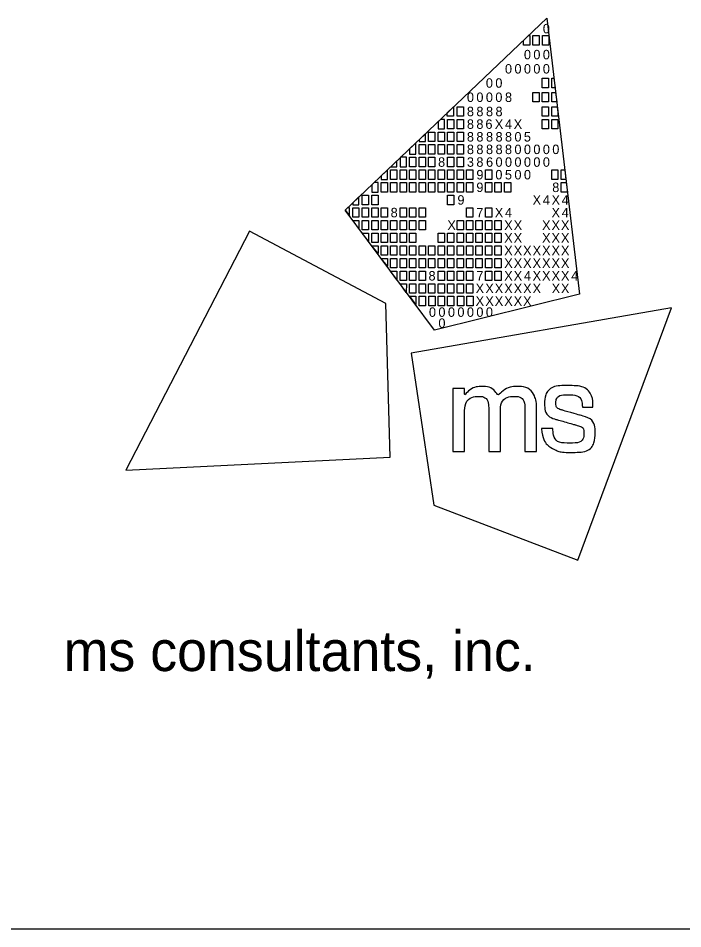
# Model space of a CAD drawing. Extents: x 0 to 34, y 0 to 22.
# Drawn here: x 32.048 to 33.205, y 2.5 to 4.086 of the extents above; entities that cross this region are included whole.
import ezdxf

# ---------------------------------------------------------------- set-up
doc = ezdxf.new("R2010")
doc.units = 0
doc.layers.add('SH_Border', color=7, linetype='Continuous')
doc.layers.add('SH_Data', color=7, linetype='Continuous')

msp = doc.modelspace()

# ---------------------------------------------------------------- linework, layer by layer
at = {"layer": 'SH_Border'}
for p, q in [((32.6175, 3.7519), (32.9688, 4.0861)), ((32.9688, 4.0861), (32.9688, 4.0861)), ((32.9688, 4.0861), (33.0253, 3.6052)), ((32.773, 3.543), (32.6175, 3.7519)), ((33.0253, 3.6052), (32.773, 3.543)), ((32, 2.5), (33.5, 2.5))]:
    msp.add_line(p, q, dxfattribs=at)
for points in [[(32.9279, 4.0472), (32.9369, 4.0558), (32.9389, 4.0558), (32.9389, 4.0393), (32.9279, 4.0393)], [(32.9444, 4.0558), (32.9554, 4.0558), (32.9554, 4.0393), (32.9444, 4.0393)], [(32.9609, 4.0558), (32.9719, 4.0558), (32.9719, 4.0393), (32.9609, 4.0393)], [(32.9606, 3.9815), (32.9716, 3.9815), (32.9716, 3.965), (32.9606, 3.965)], [(32.9771, 3.9815), (32.9811, 3.9815), (32.983, 3.965), (32.9771, 3.965)], [(32.9441, 3.9567), (32.9551, 3.9567), (32.9551, 3.9402), (32.9441, 3.9402)], [(32.9606, 3.9567), (32.9716, 3.9567), (32.9716, 3.9402), (32.9606, 3.9402)], [(32.9771, 3.9567), (32.984, 3.9567), (32.9859, 3.9402), (32.9771, 3.9402)], [(32.7953, 3.9211), (32.8064, 3.9316), (32.8064, 3.9154), (32.7953, 3.9154)], [(32.8123, 3.9319), (32.8233, 3.9319), (32.8233, 3.9154), (32.8123, 3.9154)], [(32.9606, 3.9319), (32.9716, 3.9319), (32.9716, 3.9154), (32.9606, 3.9154)], [(32.9771, 3.9319), (32.9869, 3.9319), (32.9881, 3.9218), (32.9881, 3.9154), (32.9771, 3.9154)], [(32.7958, 3.9099), (32.8068, 3.9099), (32.8068, 3.8934), (32.7958, 3.8934)], [(32.8123, 3.9099), (32.8233, 3.9099), (32.8233, 3.8934), (32.8123, 3.8934)], [(32.9606, 3.9099), (32.9716, 3.9099), (32.9716, 3.8934), (32.9606, 3.8934)], [(32.9771, 3.9099), (32.9881, 3.9099), (32.9881, 3.8934), (32.9771, 3.8934)], [(32.7627, 3.8879), (32.7737, 3.8879), (32.7737, 3.8714), (32.7627, 3.8714)], [(32.7793, 3.8879), (32.7903, 3.8879), (32.7903, 3.8714), (32.7793, 3.8714)], [(32.7958, 3.8879), (32.8068, 3.8879), (32.8068, 3.8714), (32.7958, 3.8714)], [(32.8123, 3.8879), (32.8233, 3.8879), (32.8233, 3.8714), (32.8123, 3.8714)], [(32.7462, 3.8659), (32.7572, 3.8659), (32.7572, 3.8494), (32.7462, 3.8494)], [(32.7627, 3.8659), (32.7737, 3.8659), (32.7737, 3.8494), (32.7627, 3.8494)], [(32.7793, 3.8659), (32.7903, 3.8659), (32.7903, 3.8494), (32.7793, 3.8494)], [(32.7958, 3.8659), (32.8068, 3.8659), (32.8068, 3.8494), (32.7958, 3.8494)], [(32.8123, 3.8659), (32.8233, 3.8659), (32.8233, 3.8494), (32.8123, 3.8494)], [(32.7297, 3.8439), (32.7407, 3.8439), (32.7407, 3.8273), (32.7297, 3.8273)], [(32.7462, 3.8439), (32.7572, 3.8439), (32.7572, 3.8273), (32.7462, 3.8273)], [(32.7627, 3.8439), (32.7737, 3.8439), (32.7737, 3.8273), (32.7627, 3.8273)], [(32.7958, 3.8439), (32.8068, 3.8439), (32.8068, 3.8273), (32.7958, 3.8273)], [(32.8123, 3.8439), (32.8233, 3.8439), (32.8233, 3.8273), (32.8123, 3.8273)], [(32.6967, 3.8218), (32.7077, 3.8218), (32.7077, 3.8053), (32.6967, 3.8053)], [(32.7132, 3.8218), (32.7242, 3.8218), (32.7242, 3.8053), (32.7132, 3.8053)], [(32.7297, 3.8218), (32.7407, 3.8218), (32.7407, 3.8053), (32.7297, 3.8053)], [(32.7462, 3.8218), (32.7572, 3.8218), (32.7572, 3.8053), (32.7462, 3.8053)], [(32.7627, 3.8218), (32.7737, 3.8218), (32.7737, 3.8053), (32.7627, 3.8053)], [(32.7793, 3.8218), (32.7903, 3.8218), (32.7903, 3.8053), (32.7793, 3.8053)], [(32.7958, 3.8218), (32.8068, 3.8218), (32.8068, 3.8053), (32.7958, 3.8053)], [(32.8123, 3.8218), (32.8233, 3.8218), (32.8233, 3.8053), (32.8123, 3.8053)], [(32.8288, 3.8218), (32.8398, 3.8218), (32.8398, 3.8053), (32.8288, 3.8053)], [(32.8618, 3.8218), (32.8728, 3.8218), (32.8728, 3.8053), (32.8618, 3.8053)], [(32.9771, 3.8218), (32.9881, 3.8218), (32.9881, 3.8053), (32.9771, 3.8053)], [(32.9935, 3.8218), (32.9998, 3.8218), (33.0018, 3.8053), (32.9935, 3.8053)], [(32.6802, 3.7998), (32.6912, 3.7998), (32.6912, 3.7833), (32.6802, 3.7833)], [(32.6967, 3.7998), (32.7077, 3.7998), (32.7077, 3.7833), (32.6967, 3.7833)], [(32.7132, 3.7998), (32.7242, 3.7998), (32.7242, 3.7833), (32.7132, 3.7833)], [(32.7297, 3.7998), (32.7407, 3.7998), (32.7407, 3.7833), (32.7297, 3.7833)], [(32.7462, 3.7998), (32.7572, 3.7998), (32.7572, 3.7833), (32.7462, 3.7833)], [(32.7627, 3.7998), (32.7737, 3.7998), (32.7737, 3.7833), (32.7627, 3.7833)], [(32.7793, 3.7998), (32.7903, 3.7998), (32.7903, 3.7833), (32.7793, 3.7833)], [(32.7958, 3.7998), (32.8068, 3.7998), (32.8068, 3.7833), (32.7958, 3.7833)], [(32.8123, 3.7998), (32.8233, 3.7998), (32.8233, 3.7833), (32.8123, 3.7833)], [(32.8288, 3.7998), (32.8398, 3.7998), (32.8398, 3.7833), (32.8288, 3.7833)], [(32.8618, 3.7998), (32.8728, 3.7998), (32.8728, 3.7833), (32.8618, 3.7833)], [(32.8783, 3.7998), (32.8893, 3.7998), (32.8893, 3.7833), (32.8783, 3.7833)], [(32.8947, 3.7998), (32.9057, 3.7998), (32.9057, 3.7833), (32.8947, 3.7833)], [(32.9935, 3.7998), (33.0024, 3.7998), (33.0044, 3.7833), (32.9935, 3.7833)], [(32.6471, 3.7778), (32.6581, 3.7778), (32.6581, 3.7613), (32.6471, 3.7613)], [(32.6637, 3.7778), (32.6747, 3.7778), (32.6747, 3.7613), (32.6637, 3.7613)], [(32.7958, 3.7778), (32.8068, 3.7778), (32.8068, 3.7613), (32.7958, 3.7613)], [(32.6306, 3.7558), (32.6416, 3.7558), (32.6416, 3.7393), (32.6306, 3.7393)], [(32.6471, 3.7558), (32.6581, 3.7558), (32.6581, 3.7393), (32.6471, 3.7393)], [(32.6637, 3.7558), (32.6747, 3.7558), (32.6747, 3.7393), (32.6637, 3.7393)], [(32.6802, 3.7558), (32.6912, 3.7558), (32.6912, 3.7393), (32.6802, 3.7393)], [(32.7132, 3.7558), (32.7242, 3.7558), (32.7242, 3.7393), (32.7132, 3.7393)], [(32.7297, 3.7558), (32.7407, 3.7558), (32.7407, 3.7393), (32.7297, 3.7393)], [(32.7462, 3.7558), (32.7572, 3.7558), (32.7572, 3.7393), (32.7462, 3.7393)], [(32.8288, 3.7558), (32.8398, 3.7558), (32.8398, 3.7393), (32.8288, 3.7393)], [(32.8618, 3.7558), (32.8728, 3.7558), (32.8728, 3.7393), (32.8618, 3.7393)], [(32.6306, 3.7338), (32.6416, 3.7338), (32.6416, 3.72)], [(32.6471, 3.7338), (32.6581, 3.7338), (32.6581, 3.7173), (32.6471, 3.7173)], [(32.6637, 3.7338), (32.6747, 3.7338), (32.6747, 3.7173), (32.6637, 3.7173)], [(32.6802, 3.7338), (32.6912, 3.7338), (32.6912, 3.7173), (32.6802, 3.7173)], [(32.6967, 3.7338), (32.7077, 3.7338), (32.7077, 3.7173), (32.6967, 3.7173)], [(32.7132, 3.7338), (32.7242, 3.7338), (32.7242, 3.7173), (32.7132, 3.7173)], [(32.7297, 3.7338), (32.7407, 3.7338), (32.7407, 3.7173), (32.7297, 3.7173)], [(32.7462, 3.7338), (32.7572, 3.7338), (32.7572, 3.7173), (32.7462, 3.7173)], [(32.8123, 3.7338), (32.8233, 3.7338), (32.8233, 3.7173), (32.8123, 3.7173)], [(32.8288, 3.7338), (32.8398, 3.7338), (32.8398, 3.7173), (32.8288, 3.7173)], [(32.8453, 3.7338), (32.8563, 3.7338), (32.8563, 3.7173), (32.8453, 3.7173)], [(32.8618, 3.7338), (32.8728, 3.7338), (32.8728, 3.7173), (32.8618, 3.7173)], [(32.8783, 3.7338), (32.8893, 3.7338), (32.8893, 3.7173), (32.8783, 3.7173)], [(32.6471, 3.7117), (32.6581, 3.7117), (32.6581, 3.698)], [(32.6637, 3.7117), (32.6747, 3.7117), (32.6747, 3.6952), (32.6637, 3.6952)], [(32.6802, 3.7117), (32.6912, 3.7117), (32.6912, 3.6952), (32.6802, 3.6952)], [(32.6967, 3.7117), (32.7077, 3.7117), (32.7077, 3.6952), (32.6967, 3.6952)], [(32.7132, 3.7117), (32.7242, 3.7117), (32.7242, 3.6952), (32.7132, 3.6952)], [(32.7297, 3.7117), (32.7407, 3.7117), (32.7407, 3.6952), (32.7297, 3.6952)], [(32.7793, 3.7117), (32.7903, 3.7117), (32.7903, 3.6952), (32.7793, 3.6952)], [(32.7958, 3.7117), (32.8068, 3.7117), (32.8068, 3.6952), (32.7958, 3.6952)], [(32.8123, 3.7117), (32.8233, 3.7117), (32.8233, 3.6952), (32.8123, 3.6952)], [(32.8288, 3.7117), (32.8398, 3.7117), (32.8398, 3.6952), (32.8288, 3.6952)], [(32.8453, 3.7117), (32.8563, 3.7117), (32.8563, 3.6952), (32.8453, 3.6952)], [(32.8618, 3.7117), (32.8728, 3.7117), (32.8728, 3.6952), (32.8618, 3.6952)], [(32.8783, 3.7117), (32.8893, 3.7117), (32.8893, 3.6952), (32.8783, 3.6952)], [(32.6637, 3.6897), (32.6747, 3.6897), (32.6747, 3.676)], [(32.6747, 3.6897), (32.6747, 3.6897), (32.6747, 3.6897)], [(32.6802, 3.6897), (32.6912, 3.6897), (32.6912, 3.6732), (32.6802, 3.6732)], [(32.6967, 3.6897), (32.7077, 3.6897), (32.7077, 3.6732), (32.6967, 3.6732)], [(32.7132, 3.6897), (32.7242, 3.6897), (32.7242, 3.6732), (32.7132, 3.6732)], [(32.7297, 3.6897), (32.7407, 3.6897), (32.7407, 3.6732), (32.7297, 3.6732)], [(32.7462, 3.6897), (32.7572, 3.6897), (32.7572, 3.6732), (32.7462, 3.6732)], [(32.7627, 3.6897), (32.7737, 3.6897), (32.7737, 3.6732), (32.7627, 3.6732)], [(32.7793, 3.6897), (32.7903, 3.6897), (32.7903, 3.6732), (32.7793, 3.6732)], [(32.7958, 3.6897), (32.8068, 3.6897), (32.8068, 3.6732), (32.7958, 3.6732)], [(32.8123, 3.6897), (32.8233, 3.6897), (32.8233, 3.6732), (32.8123, 3.6732)], [(32.8288, 3.6897), (32.8398, 3.6897), (32.8398, 3.6732), (32.8288, 3.6732)], [(32.8453, 3.6897), (32.8563, 3.6897), (32.8563, 3.6732), (32.8453, 3.6732)], [(32.8618, 3.6897), (32.8728, 3.6897), (32.8728, 3.6732), (32.8618, 3.6732)], [(32.8783, 3.6897), (32.8893, 3.6897), (32.8893, 3.6732), (32.8783, 3.6732)], [(32.6802, 3.6677), (32.6912, 3.6677), (32.6912, 3.654)], [(32.6967, 3.6677), (32.7077, 3.6677), (32.7077, 3.6512), (32.6967, 3.6512)], [(32.7132, 3.6677), (32.7242, 3.6677), (32.7242, 3.6512), (32.7132, 3.6512)], [(32.7297, 3.6677), (32.7407, 3.6677), (32.7407, 3.6512), (32.7297, 3.6512)], [(32.7462, 3.6677), (32.7572, 3.6677), (32.7572, 3.6512), (32.7462, 3.6512)], [(32.7627, 3.6677), (32.7737, 3.6677), (32.7737, 3.6512), (32.7627, 3.6512)], [(32.7793, 3.6677), (32.7903, 3.6677), (32.7903, 3.6512), (32.7793, 3.6512)], [(32.7958, 3.6677), (32.8068, 3.6677), (32.8068, 3.6512), (32.7958, 3.6512)], [(32.8123, 3.6677), (32.8233, 3.6677), (32.8233, 3.6512), (32.8123, 3.6512)], [(32.8288, 3.6677), (32.8398, 3.6677), (32.8398, 3.6512), (32.8288, 3.6512)], [(32.8453, 3.6677), (32.8563, 3.6677), (32.8563, 3.6512), (32.8453, 3.6512)], [(32.8618, 3.6677), (32.8728, 3.6677), (32.8728, 3.6512), (32.8618, 3.6512)], [(32.8783, 3.6677), (32.8893, 3.6677), (32.8893, 3.6512), (32.8783, 3.6512)], [(32.7077, 3.6305), (32.6965, 3.6457), (32.7077, 3.6457)], [(32.7132, 3.6457), (32.7242, 3.6457), (32.7242, 3.6292), (32.7132, 3.6292)], [(32.7297, 3.6457), (32.7407, 3.6457), (32.7407, 3.6292), (32.7297, 3.6292)], [(32.7462, 3.6457), (32.7572, 3.6457), (32.7572, 3.6292), (32.7462, 3.6292)], [(32.7793, 3.6457), (32.7903, 3.6457), (32.7903, 3.6292), (32.7793, 3.6292)], [(32.7958, 3.6457), (32.8068, 3.6457), (32.8068, 3.6292), (32.7958, 3.6292)], [(32.8123, 3.6457), (32.8233, 3.6457), (32.8233, 3.6292), (32.8123, 3.6292)], [(32.8288, 3.6457), (32.8398, 3.6457), (32.8398, 3.6292), (32.8288, 3.6292)], [(32.8618, 3.6457), (32.8728, 3.6457), (32.8728, 3.6292), (32.8618, 3.6292)], [(32.8783, 3.6457), (32.8893, 3.6457), (32.8893, 3.6292), (32.8783, 3.6292)], [(32.724, 3.6082), (32.7132, 3.6237), (32.7242, 3.6237)], [(32.7297, 3.6237), (32.7407, 3.6237), (32.7407, 3.6072), (32.7297, 3.6072)], [(32.7462, 3.6237), (32.7572, 3.6237), (32.7572, 3.6072), (32.7462, 3.6072)], [(32.7627, 3.6237), (32.7737, 3.6237), (32.7737, 3.6072), (32.7627, 3.6072)], [(32.7793, 3.6237), (32.7903, 3.6237), (32.7903, 3.6072), (32.7793, 3.6072)], [(32.7958, 3.6237), (32.8068, 3.6237), (32.8068, 3.6072), (32.7958, 3.6072)], [(32.8123, 3.6237), (32.8233, 3.6237), (32.8233, 3.6072), (32.8123, 3.6072)], [(32.8288, 3.6237), (32.8398, 3.6237), (32.8398, 3.6072), (32.8288, 3.6072)], [(32.7302, 3.6017), (32.7407, 3.6017), (32.7408, 3.5875)], [(32.7463, 3.6017), (32.7573, 3.6017), (32.7573, 3.5852), (32.7463, 3.5852)], [(32.763, 3.6017), (32.774, 3.6017), (32.774, 3.5852), (32.763, 3.5852)], [(32.7794, 3.6017), (32.7904, 3.6017), (32.7904, 3.5852), (32.7794, 3.5852)], [(32.796, 3.6017), (32.807, 3.6017), (32.807, 3.5852), (32.796, 3.5852)], [(32.8129, 3.6017), (32.8239, 3.6017), (32.8239, 3.5851), (32.8129, 3.5851)], [(32.8296, 3.6017), (32.8406, 3.6017), (32.8406, 3.5851), (32.8296, 3.5851)]]:
    msp.add_lwpolyline(points, close=True, dxfattribs=at)
for points in [[(32.7903, 3.9099), (32.7836, 3.9099), (32.7793, 3.9058), (32.7793, 3.8934), (32.7903, 3.8934), (32.7903, 3.9099)], [(32.7572, 3.8849), (32.7462, 3.8744), (32.7462, 3.8714), (32.7572, 3.8714), (32.7572, 3.8849)], [(32.7407, 3.8691), (32.7297, 3.8587), (32.7297, 3.8494), (32.7407, 3.8494), (32.7407, 3.8691)], [(32.7242, 3.8439), (32.7141, 3.8439), (32.7132, 3.843), (32.7132, 3.8273), (32.7242, 3.8273), (32.7242, 3.8439)], [(32.7077, 3.8377), (32.6968, 3.8273), (32.7077, 3.8273), (32.7077, 3.8377)], [(32.6912, 3.822), (32.6802, 3.8115), (32.6802, 3.8053), (32.6912, 3.8053), (32.6912, 3.822)], [(32.6747, 3.7998), (32.6679, 3.7998), (32.6637, 3.7958), (32.6637, 3.7833), (32.6747, 3.7833), (32.6747, 3.7998)], [(32.6416, 3.7749), (32.6306, 3.7644), (32.6306, 3.7613), (32.6416, 3.7613), (32.6416, 3.7749)], [(32.6251, 3.7558), (32.6216, 3.7558), (32.6175, 3.7519), (32.6251, 3.7417), (32.6251, 3.7558)], [(32.4512, 3.7149), (32.2359, 3.2988), (32.6956, 3.3215), (32.6884, 3.5892), (32.4512, 3.7149)], [(33.0229, 3.1422), (33.1859, 3.5814), (32.7324, 3.5029), (32.7722, 3.2381), (33.0229, 3.1422)]]:
    msp.add_lwpolyline(points, dxfattribs=at)
for points in [[(32.8048, 3.3315), (32.8048, 3.3315), (32.8048, 3.4409), (32.8048, 3.4409), (32.8048, 3.4409), (32.8255, 3.4409), (32.8255, 3.4409), (32.8255, 3.4409), (32.8255, 3.4297), (32.8255, 3.4297), (32.8346, 3.4399), (32.8457, 3.4445), (32.8555, 3.4445), (32.8688, 3.4445), (32.8791, 3.4372), (32.8837, 3.4266), (32.8915, 3.4381), (32.905, 3.4446), (32.9166, 3.4446), (32.9325, 3.4446), (32.9451, 3.435), (32.9494, 3.4213), (32.9494, 3.4212), (32.9494, 3.4212), (32.9494, 3.4212), (32.9501, 3.419), (32.9506, 3.4172), (32.9506, 3.4071), (32.9506, 3.4071), (32.9506, 3.3314), (32.9506, 3.3314), (32.9506, 3.3314), (32.9303, 3.3314), (32.9303, 3.3314), (32.9303, 3.3314), (32.9303, 3.4048), (32.9303, 3.4048), (32.9303, 3.4201), (32.9219, 3.4274), (32.911, 3.4274), (32.8995, 3.4274), (32.8879, 3.4171), (32.8879, 3.4001), (32.8879, 3.4001), (32.8879, 3.3315), (32.8879, 3.3315), (32.8879, 3.3315), (32.8674, 3.3315), (32.8674, 3.3315), (32.8674, 3.3315), (32.8674, 3.4059), (32.8674, 3.4059), (32.8674, 3.4203), (32.8588, 3.4274), (32.8496, 3.4274), (32.8384, 3.4274), (32.8254, 3.417), (32.8254, 3.3962), (32.8254, 3.3962), (32.8254, 3.3315), (32.8254, 3.3315), (32.8254, 3.3315), (32.8048, 3.3315), (32.8048, 3.3315)], [(32.9595, 3.3709), (32.9595, 3.3709), (32.9595, 3.3717), (32.9595, 3.3717), (32.9595, 3.3717), (32.9603, 3.3717), (32.9603, 3.3717), (32.9603, 3.3717), (32.9783, 3.3717), (32.9783, 3.3717), (32.9783, 3.3717), (32.9789, 3.3717), (32.9789, 3.3717), (32.9789, 3.3717), (32.979, 3.371), (32.979, 3.371), (32.9803, 3.3554), (32.9887, 3.346), (33.009, 3.346), (33.0273, 3.346), (33.0333, 3.3554), (33.0333, 3.3631), (33.0333, 3.3732), (33.0256, 3.3758), (33.0175, 3.378), (33.0175, 3.378), (32.987, 3.3867), (32.987, 3.3867), (32.972, 3.3909), (32.9648, 3.4019), (32.9648, 3.4142), (32.9648, 3.4303), (32.9768, 3.4462), (33.0052, 3.4462), (33.0348, 3.4462), (33.0489, 3.4285), (33.0489, 3.4095), (33.0489, 3.4095), (33.0489, 3.4087), (33.0489, 3.4087), (33.0489, 3.4087), (33.0482, 3.4087), (33.0482, 3.4087), (33.0482, 3.4087), (33.0312, 3.4087), (33.0312, 3.4087), (33.0312, 3.4087), (33.0305, 3.4087), (33.0305, 3.4087), (33.0305, 3.4087), (33.0305, 3.4094), (33.0305, 3.4094), (33.0301, 3.4208), (33.0226, 3.43), (33.0056, 3.43), (32.9891, 3.43), (32.9843, 3.4218), (32.9843, 3.4157), (32.9843, 3.4108), (32.9869, 3.4059), (32.9959, 3.4033), (32.9959, 3.4033), (33.0255, 3.3948), (33.0255, 3.3948), (33.0462, 3.3889), (33.0527, 3.3777), (33.0527, 3.3639), (33.0527, 3.3462), (33.041, 3.3298), (33.0087, 3.3298), (32.9952, 3.3298), (32.9877, 3.3321), (32.9823, 3.3348), (32.969, 3.3414), (32.9609, 3.3536), (32.9595, 3.3709)]]:
    msp.add_open_spline(points, degree=3, dxfattribs=at)
at = {"layer": 'SH_Data'}
msp.add_line((32.75, 3.5), (32.75, 3.5), dxfattribs=at)

# ---------------------------------------------------------------- texts
at = {"layer": 'SH_Border'}
for s, height, p in [('0', 0.0165, (32.9617, 4.0597)), ('0', 0.0165, (32.9288, 4.0145)), ('0', 0.0165, (32.9452, 4.0145)), ('0', 0.0165, (32.9617, 4.0145)), ('0', 0.0165, (32.8958, 3.9897)), ('0', 0.0165, (32.9123, 3.9897)), ('0', 0.0165, (32.9288, 3.9897)), ('0', 0.0165, (32.9452, 3.9897)), ('0', 0.0165, (32.9617, 3.9897)), ('0', 0.0165, (32.8625, 3.965)), ('0', 0.0165, (32.879, 3.965)), ('0', 0.0165, (32.8295, 3.9402)), ('0', 0.0165, (32.846, 3.9402)), ('0', 0.0165, (32.8625, 3.9402)), ('0', 0.0165, (32.879, 3.9402)), ('8', 0.0165, (32.8958, 3.9402)), ('8', 0.0165, (32.8295, 3.9154)), ('8', 0.0165, (32.846, 3.9154)), ('8', 0.0165, (32.8628, 3.9154)), ('8', 0.0165, (32.8793, 3.9154)), ('8', 0.0165, (32.8295, 3.8934)), ('8', 0.0165, (32.846, 3.8934)), ('6', 0.0165, (32.8618, 3.8934)), ('X', 0.0165, (32.8781, 3.8934)), ('4', 0.0165, (32.8958, 3.8934)), ('X', 0.0165, (32.911, 3.8934)), ('8', 0.0165, (32.8295, 3.8713)), ('8', 0.0165, (32.846, 3.8713)), ('8', 0.0165, (32.8628, 3.8713)), ('8', 0.0165, (32.8794, 3.8713)), ('8', 0.0165, (32.8958, 3.8713)), ('0', 0.0165, (32.9123, 3.8713)), ('5', 0.0165, (32.9287, 3.8713)), ('8', 0.0165, (32.8295, 3.8494)), ('8', 0.0165, (32.846, 3.8494)), ('8', 0.0165, (32.8628, 3.8494)), ('8', 0.0165, (32.8794, 3.8494)), ('8', 0.0165, (32.8958, 3.8494)), ('0', 0.0165, (32.9123, 3.8494)), ('0', 0.0165, (32.9288, 3.8494)), ('0', 0.0165, (32.9452, 3.8494)), ('0', 0.0165, (32.9617, 3.8494)), ('0', 0.0165, (32.9782, 3.8494)), ('8', 0.0165, (32.7793, 3.8273)), ('3', 0.0165, (32.8295, 3.8273)), ('8', 0.0165, (32.846, 3.8273)), ('6', 0.0165, (32.8629, 3.8273)), ('0', 0.0165, (32.8793, 3.8273)), ('0', 0.0165, (32.8958, 3.8273)), ('0', 0.0165, (32.9123, 3.8273)), ('0', 0.0165, (32.9288, 3.8273)), ('0', 0.0165, (32.9452, 3.8273)), ('0', 0.0165, (32.9617, 3.8273)), ('9', 0.0165, (32.846, 3.8053)), ('0', 0.0165, (32.879, 3.8053)), ('5', 0.0165, (32.8957, 3.8053)), ('0', 0.0165, (32.9123, 3.8053)), ('0', 0.0165, (32.9288, 3.8053)), ('9', 0.0165, (32.846, 3.7833)), ('8', 0.0165, (32.9781, 3.7833)), ('9', 0.0165, (32.813, 3.7613)), ('X', 0.0165, (32.9439, 3.7613)), ('4', 0.0165, (32.9617, 3.7613)), ('X', 0.0165, (32.9769, 3.7613)), ('4', 0.0165, (32.9946, 3.7613)), ('8', 0.0165, (32.6967, 3.7393)), ('7', 0.0165, (32.846, 3.7393)), ('X', 0.0165, (32.8781, 3.7393)), ('4', 0.0165, (32.8958, 3.7393)), ('X', 0.0165, (32.9769, 3.7393)), ('4', 0.0165, (32.9946, 3.7393)), ('X', 0.0165, (32.7955, 3.7173)), ('X', 0.0165, (32.8945, 3.7173)), ('X', 0.0165, (32.911, 3.7173)), ('X', 0.0165, (32.9604, 3.7173)), ('X', 0.0165, (32.9769, 3.7173)), ('X', 0.0165, (32.9933, 3.7173)), ('X', 0.0165, (32.8945, 3.6952)), ('X', 0.0165, (32.911, 3.6952)), ('X', 0.0165, (32.9604, 3.6952)), ('X', 0.0165, (32.9769, 3.6952)), ('X', 0.0165, (32.9933, 3.6952)), ('X', 0.0165, (32.8945, 3.6732)), ('X', 0.0165, (32.911, 3.6732)), ('X', 0.0165, (32.9274, 3.6732)), ('X', 0.0165, (32.9439, 3.6732)), ('X', 0.0165, (32.9604, 3.6732)), ('X', 0.0165, (32.9769, 3.6732)), ('X', 0.0165, (32.9933, 3.6732)), ('X', 0.0165, (32.8945, 3.6512)), ('X', 0.0165, (32.911, 3.6512)), ('X', 0.0165, (32.9274, 3.6512)), ('X', 0.0165, (32.9439, 3.6512)), ('X', 0.0165, (32.9604, 3.6512)), ('X', 0.0165, (32.9769, 3.6512)), ('X', 0.0165, (32.9933, 3.6512)), ('8', 0.0165, (32.7627, 3.6292)), ('7', 0.0165, (32.846, 3.6292)), ('X', 0.0165, (32.8945, 3.6292)), ('X', 0.0165, (32.911, 3.6292)), ('4', 0.0165, (32.9288, 3.6292)), ('X', 0.0165, (32.9439, 3.6292)), ('X', 0.0165, (32.9604, 3.6292)), ('X', 0.0165, (32.9769, 3.6292)), ('X', 0.0165, (32.9933, 3.6292)), ('4', 0.0165, (33.0111, 3.6292)), ('X', 0.0165, (32.8447, 3.6072)), ('X', 0.0165, (32.8616, 3.6072)), ('X', 0.0165, (32.878, 3.6072)), ('X', 0.0165, (32.8945, 3.6072)), ('X', 0.0165, (32.911, 3.6072)), ('X', 0.0165, (32.9274, 3.6072)), ('X', 0.0165, (32.9439, 3.6072)), ('X', 0.0165, (32.9771, 3.6072)), ('X', 0.0165, (32.9933, 3.6072)), ('X', 0.0165, (32.8447, 3.5851)), ('X', 0.0165, (32.8616, 3.5851)), ('X', 0.0165, (32.878, 3.5851)), ('X', 0.0165, (32.8945, 3.5851)), ('X', 0.0165, (32.911, 3.5851)), ('X', 0.0165, (32.9274, 3.5851)), ('0', 0.0165, (32.7634, 3.5659)), ('0', 0.0165, (32.7799, 3.5659)), ('0', 0.0165, (32.7965, 3.5659)), ('0', 0.0165, (32.813, 3.5659)), ('0', 0.0165, (32.8295, 3.5659)), ('0', 0.0165, (32.846, 3.5659)), ('0', 0.0165, (32.8625, 3.5659)), ('0', 0.0165, (32.7799, 3.5467)), ('ms consultants, inc.', 0.07, (32.1273, 2.9489))]:
    msp.add_text(s, height=height, rotation=360, dxfattribs=at).set_placement(p)

doc.saveas('drawing.dxf')
